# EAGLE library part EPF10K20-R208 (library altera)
EPF10K20 FLEX 10K family
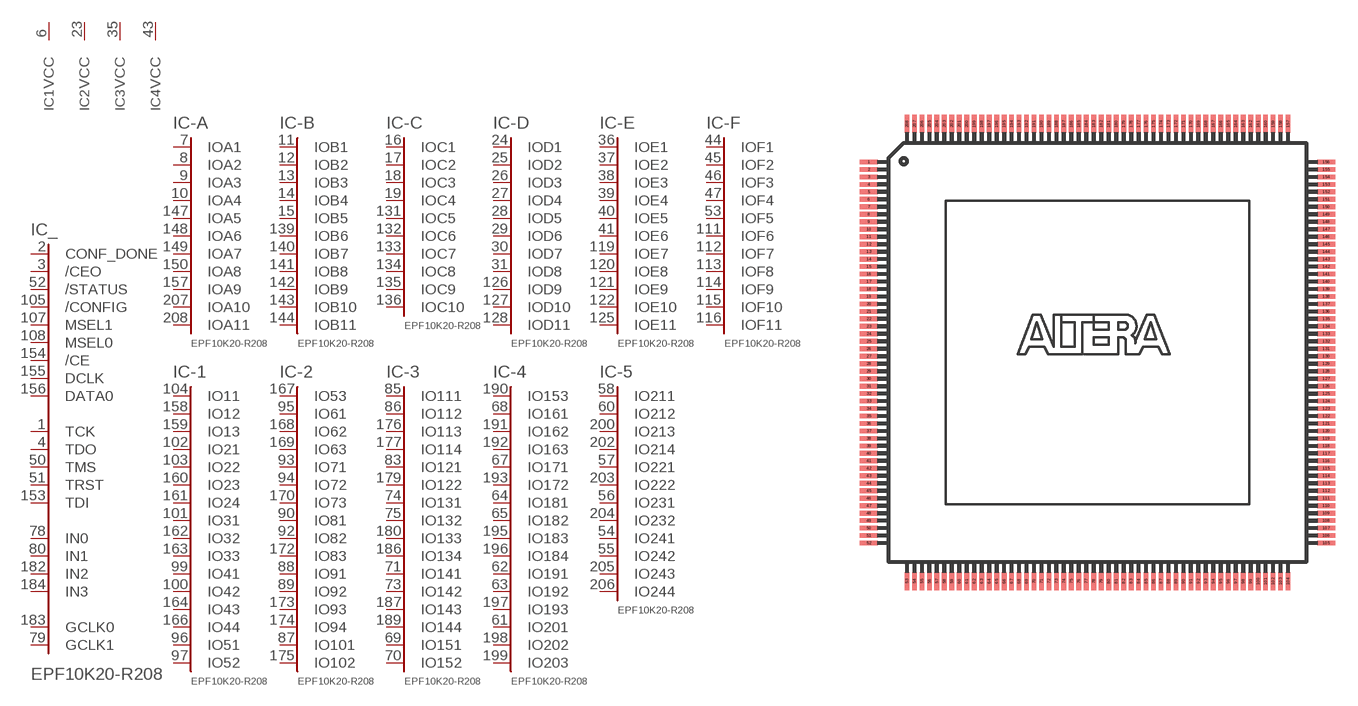
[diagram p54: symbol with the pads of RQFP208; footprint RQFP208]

Designator prefix IC; gates _=100R240C -A=A11 -B=B11 -C=C10 -D=D11 -E=E11 -F=F11 -1=52-20R -2=102-20R -3=152-20R -4=203-20R -5=244-20R 1=VCCINT 2=VCCINT 3=VCCINT 4=VCCINT 5=VCCINT 6=VCCINT 7=VCCINT 8=VCCINT 9=VCCINT 10=VCCINT 11=VCCINT 12=VCCINT 13=VCCIO 14=VCCIO 15=VCCIO 16=VCCIO 17=VCCIO 18=VCCIO 19=VCCIO 20=VCCIO 21=VCCIO 22=VCCIO 23=VCCIO 24=VCCIO 25=VCCIO 26=VCCIO 27=GNDINT 28=GNDINT 29=GNDINT 30=GNDINT 31=GNDINT 32=GNDINT 33=GNDINT 34=GNDINT 35=GNDINT 36=GNDIO 37=GNDIO 38=GNDIO 39=GNDIO 40=GNDIO 41=GNDIO 42=GNDIO 43=GNDIO 44=GNDIO 45=GNDIO 46=GNDIO 47=GNDIO

## EPF10K20-R208 (MPN: EPF10K20RC208-3N; OC_FARNELL: 1549383; OC_NEWARK: 51R8880)  [RQFP208]
1  _:TCK
2  _:CONF_DONE  in
3  _:/CEO  in
4  _:TDO
5  13:VCCIO  pwr
6  1:VCC  pwr
7  -A:IOA1
8  -A:IOA2
9  -A:IOA3
10  -A:IOA4
11  -B:IOB1
12  -B:IOB2
13  -B:IOB3
14  -B:IOB4
15  -B:IOB5
16  -C:IOC1
17  -C:IOC2
18  -C:IOC3
19  -C:IOC4
20  36:GNDIO  pwr
21  27:GND  pwr
22  14:VCCIO  pwr
23  2:VCC  pwr
24  -D:IOD1
25  -D:IOD2
26  -D:IOD3
27  -D:IOD4
28  -D:IOD5
29  -D:IOD6
30  -D:IOD7
31  -D:IOD8
32  37:GNDIO  pwr
33  28:GND  pwr
34  15:VCCIO  pwr
35  3:VCC  pwr
36  -E:IOE1
37  -E:IOE2
38  -E:IOE3
39  -E:IOE4
40  -E:IOE5
41  -E:IOE6
42  16:VCCIO  pwr
43  4:VCC  pwr
44  -F:IOF1
45  -F:IOF2
46  -F:IOF3
47  -F:IOF4
48  38:GNDIO  pwr
49  29:GND  pwr
50  _:TMS
51  _:TRST
52  _:/STATUS  in
53  -F:IOF5
54  -5:IO241
55  -5:IO242
56  -5:IO231
57  -5:IO221
58  -5:IO211
59  39:GNDIO  pwr
60  -5:IO212
61  -4:IO201
62  -4:IO191
63  -4:IO192
64  -4:IO181
65  -4:IO182
66  17:VCCIO  pwr
67  -4:IO171
68  -4:IO161
69  -3:IO151
70  -3:IO152
71  -3:IO141
72  40:GNDIO  pwr
73  -3:IO142
74  -3:IO131
75  -3:IO132
76  5:VCC  pwr
77  6:VCC  pwr
78  _:IN0  in
79  _:GCLK1  in
80  _:IN1  in
81  30:GND  pwr
82  31:GND  pwr
83  -3:IO121
84  18:VCCIO  pwr
85  -3:IO111
86  -3:IO112
87  -2:IO101
88  -2:IO91
89  -2:IO92
90  -2:IO81
91  41:GNDIO  pwr
92  -2:IO82
93  -2:IO71
94  -2:IO72
95  -2:IO61
96  -1:IO51
97  -1:IO52
98  19:VCCIO  pwr
99  -1:IO41
100  -1:IO42
101  -1:IO31
102  -1:IO21
103  -1:IO22
104  -1:IO11
105  _:/CONFIG  in
106  7:VCC  pwr
107  _:MSEL1  in
108  _:MSEL0  in
109  8:VCC  pwr
110  20:VCCIO  pwr
111  -F:IOF6
112  -F:IOF7
113  -F:IOF8
114  -F:IOF9
115  -F:IOF10
116  -F:IOF11
117  9:VCC  pwr
118  21:VCCIO  pwr
119  -E:IOE7
120  -E:IOE8
121  -E:IOE9
122  -E:IOE10
123  32:GND  pwr
124  42:GNDIO  pwr
125  -E:IOE11
126  -D:IOD9
127  -D:IOD10
128  -D:IOD11
129  33:GND  pwr
130  43:GNDIO  pwr
131  -C:IOC5
132  -C:IOC6
133  -C:IOC7
134  -C:IOC8
135  -C:IOC9
136  -C:IOC10
137  10:VCC  pwr
138  22:VCCIO  pwr
139  -B:IOB6
140  -B:IOB7
141  -B:IOB8
142  -B:IOB9
143  -B:IOB10
144  -B:IOB11
145  11:VCC  pwr
146  23:VCCIO  pwr
147  -A:IOA5
148  -A:IOA6
149  -A:IOA7
150  -A:IOA8
151  34:GND  pwr
152  44:GNDIO  pwr
153  _:TDI
154  _:/CE  in
155  _:DCLK  in
156  _:DATA0  in
157  -A:IOA9
158  -1:IO12
159  -1:IO13
160  -1:IO23
161  -1:IO24
162  -1:IO32
163  -1:IO33
164  -1:IO43
165  24:VCCIO  pwr
166  -1:IO44
167  -2:IO53
168  -2:IO62
169  -2:IO63
170  -2:IO73
171  45:GNDIO  pwr
172  -2:IO83
173  -2:IO93
174  -2:IO94
175  -2:IO102
176  -3:IO113
177  -3:IO114
178  25:VCCIO  pwr
179  -3:IO122
180  -3:IO133
181  12:VCC  pwr
182  _:IN2  in
183  _:GCLK0  in
184  _:IN3  in
185  35:GND  pwr
186  -3:IO134
187  -3:IO143
188  46:GNDIO  pwr
189  -3:IO144
190  -4:IO153
191  -4:IO162
192  -4:IO163
193  -4:IO172
194  26:VCCIO  pwr
195  -4:IO183
196  -4:IO184
197  -4:IO193
198  -4:IO202
199  -4:IO203
200  -5:IO213
201  47:GNDIO  pwr
202  -5:IO214
203  -5:IO222
204  -5:IO232
205  -5:IO243
206  -5:IO244
207  -A:IOA10
208  -A:IOA11

## Footprint RQFP208 (pad centres in mm)
Power Quad Flat Pack
smd 1.2 x 0.32: 1 -15.3,12.75; 2 -15.3,12.25; 3 -15.3,11.75; 4 -15.3,11.25; 5 -15.3,10.75; 6 -15.3,10.25; 7 -15.3,9.75; 8 -15.3,9.25; 9 -15.3,8.75; 10 -15.3,8.25; 11 -15.3,7.75; 12 -15.3,7.25; 13 -15.3,6.75; 14 -15.3,6.25; 15 -15.3,5.75; 16 -15.3,5.25; 17 -15.3,4.75; 18 -15.3,4.25; 19 -15.3,3.75; 20 -15.3,3.25; 21 -15.3,2.75; 22 -15.3,2.25; 23 -15.3,1.75; 24 -15.3,1.25; 25 -15.3,0.75; 26 -15.3,0.25; 27 -15.3,-0.25; 28 -15.3,-0.75; 29 -15.3,-1.25; 30 -15.3,-1.75; 31 -15.3,-2.25; 32 -15.3,-2.75; 33 -15.3,-3.25; 34 -15.3,-3.75; 35 -15.3,-4.25; 36 -15.3,-4.75; 37 -15.3,-5.25; 38 -15.3,-5.75; 39 -15.3,-6.25; 40 -15.3,-6.75; 41 -15.3,-7.25; 42 -15.3,-7.75; 43 -15.3,-8.25; 44 -15.3,-8.75; 45 -15.3,-9.25; 46 -15.3,-9.75; 47 -15.3,-10.25; 48 -15.3,-10.75; 49 -15.3,-11.25; 50 -15.3,-11.75; 51 -15.3,-12.25; 52 -15.3,-12.75; 105 15.3,-12.75; 106 15.3,-12.25; 107 15.3,-11.75; 108 15.3,-11.25; 109 15.3,-10.75; 110 15.3,-10.25; 111 15.3,-9.75; 112 15.3,-9.25; 113 15.3,-8.75; 114 15.3,-8.25; 115 15.3,-7.75; 116 15.3,-7.25; 117 15.3,-6.75; 118 15.3,-6.25; 119 15.3,-5.75; 120 15.3,-5.25; 121 15.3,-4.75; 122 15.3,-4.25; 123 15.3,-3.75; 124 15.3,-3.25; 125 15.3,-2.75; 126 15.3,-2.25; 127 15.3,-1.75; 128 15.3,-1.25; 129 15.3,-0.75; 130 15.3,-0.25; 131 15.3,0.25; 132 15.3,0.75; 133 15.3,1.25; 134 15.3,1.75; 135 15.3,2.25; 136 15.3,2.75; 137 15.3,3.25; 138 15.3,3.75; 139 15.3,4.25; 140 15.3,4.75; 141 15.3,5.25; 142 15.3,5.75; 143 15.3,6.25; 144 15.3,6.75; 145 15.3,7.25; 146 15.3,7.75; 147 15.3,8.25; 148 15.3,8.75; 149 15.3,9.25; 150 15.3,9.75; 151 15.3,10.25; 152 15.3,10.75; 153 15.3,11.25; 154 15.3,11.75; 155 15.3,12.25; 156 15.3,12.75
smd 0.32 x 1.2: 53 -12.75,-15.3; 54 -12.25,-15.3; 55 -11.75,-15.3; 56 -11.25,-15.3; 57 -10.75,-15.3; 58 -10.25,-15.3; 59 -9.75,-15.3; 60 -9.25,-15.3; 61 -8.75,-15.3; 62 -8.25,-15.3; 63 -7.75,-15.3; 64 -7.25,-15.3; 65 -6.75,-15.3; 66 -6.25,-15.3; 67 -5.75,-15.3; 68 -5.25,-15.3; 69 -4.75,-15.3; 70 -4.25,-15.3; 71 -3.75,-15.3; 72 -3.25,-15.3; 73 -2.75,-15.3; 74 -2.25,-15.3; 75 -1.75,-15.3; 76 -1.25,-15.3; 77 -0.75,-15.3; 78 -0.25,-15.3; 79 0.25,-15.3; 80 0.75,-15.3; 81 1.25,-15.3; 82 1.75,-15.3; 83 2.25,-15.3; 84 2.75,-15.3; 85 3.25,-15.3; 86 3.75,-15.3; 87 4.25,-15.3; 88 4.75,-15.3; 89 5.25,-15.3; 90 5.75,-15.3; 91 6.25,-15.3; 92 6.75,-15.3; 93 7.25,-15.3; 94 7.75,-15.3; 95 8.25,-15.3; 96 8.75,-15.3; 97 9.25,-15.3; 98 9.75,-15.3; 99 10.25,-15.3; 100 10.75,-15.3; 101 11.25,-15.3; 102 11.75,-15.3; 103 12.25,-15.3; 104 12.75,-15.3; 157 12.75,15.3; 158 12.25,15.3; 159 11.75,15.3; 160 11.25,15.3; 161 10.75,15.3; 162 10.25,15.3; 163 9.75,15.3; 164 9.25,15.3; 165 8.75,15.3; 166 8.25,15.3; 167 7.75,15.3; 168 7.25,15.3; 169 6.75,15.3; 170 6.25,15.3; 171 5.75,15.3; 172 5.25,15.3; 173 4.75,15.3; 174 4.25,15.3; 175 3.75,15.3; 176 3.25,15.3; 177 2.75,15.3; 178 2.25,15.3; 179 1.75,15.3; 180 1.25,15.3; 181 0.75,15.3; 182 0.25,15.3; 183 -0.25,15.3; 184 -0.75,15.3; 185 -1.25,15.3; 186 -1.75,15.3; 187 -2.25,15.3; 188 -2.75,15.3; 189 -3.25,15.3; 190 -3.75,15.3; 191 -4.25,15.3; 192 -4.75,15.3; 193 -5.25,15.3; 194 -5.75,15.3; 195 -6.25,15.3; 196 -6.75,15.3; 197 -7.25,15.3; 198 -7.75,15.3; 199 -8.25,15.3; 200 -8.75,15.3; 201 -9.25,15.3; 202 -9.75,15.3; 203 -10.25,15.3; 204 -10.75,15.3; 205 -11.25,15.3; 206 -11.75,15.3; 207 -12.25,15.3; 208 -12.75,15.3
